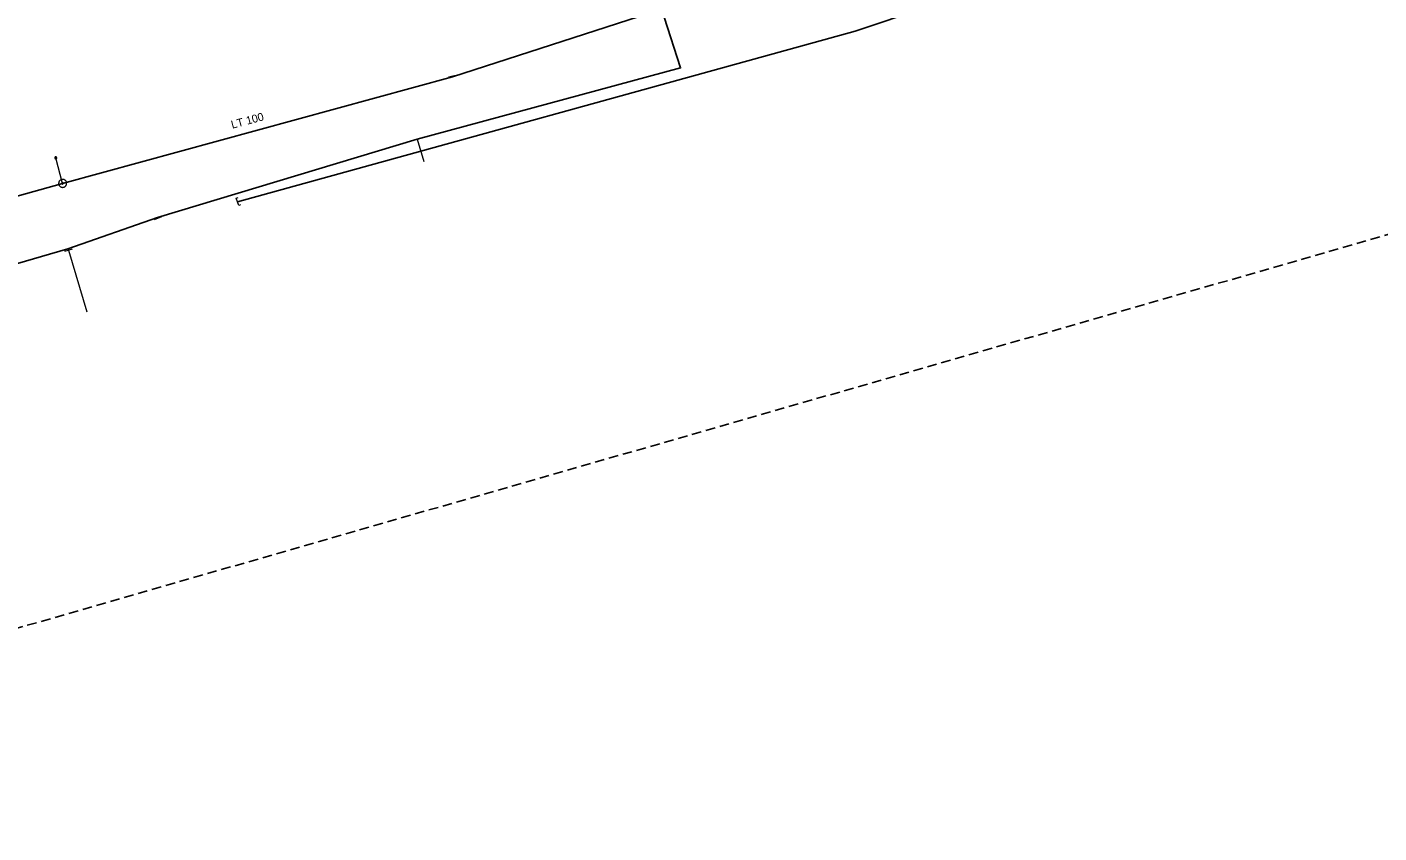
# Model space of a CAD drawing. Extents: x -690254 to -689100, y -975264 to -974703.
# Drawn here: x -690085.5 to -689916.6, y -975238.2 to -975137.4 of the extents above; entities that cross this region are included whole.
import ezdxf

# ---------------------------------------------------------------- set-up
doc = ezdxf.new("R2010")
doc.units = 0
doc.header["$LTSCALE"] = 0.4
doc.linetypes.add('MEDIUM_DASHED', pattern=[4.5, 3, -1.5])
for name, color, linetype, lineweight in [('1', 7, 'Continuous', 13), ('13', 7, 'Continuous', 13), ('14', 7, 'Continuous', 13), ('17', 7, 'Continuous', 25), ('34', 7, 'Continuous', 13), ('47', 7, 'Continuous', 13), ('63', 7, 'MEDIUM_DASHED', 25), ('9', 7, 'Continuous', 13)]:
    doc.layers.add(name, color=color, linetype=linetype, lineweight=lineweight)

msp = doc.modelspace()

# ---------------------------------------------------------------- linework, layer by layer
at = {"layer": '13'}
for p, q in [((-690036.781, -975151.448), (-690035.964, -975154.234)), ((-690080.365, -975165.332), (-690078.047, -975173.009))]:
    msp.add_line(p, q, dxfattribs=at)
at = {"layer": '14'}
for p, q in [((-690032.389, -975143.625), (-690032.41, -975143.539)), ((-690081.085, -975156.962), (-690081.941, -975153.772)), ((-690069.227, -975161.229), (-690069.19, -975161.329)), ((-690080.424, -975165.129), (-690080.365, -975165.332))]:
    msp.add_line(p, q, dxfattribs=at)
at = {"layer": '17'}
msp.add_line((-690081.085, -975156.962), (-690116.8, -975166.92), dxfattribs=at)
for points in [[(-689651.896, -975035.605), (-689702.719, -975051.484), (-689800.052, -975078.399), (-689860.597, -975095.177), (-689913.514, -975110.178), (-689937.55, -975117.079), (-689948.793, -975119.833), (-689957.109, -975122.39), (-689986.109, -975129.956), (-690002.122, -975134.99), (-690005.949, -975136.193), (-690003.879, -975142.529), (-690036.781, -975151.448), (-690069.227, -975161.229), (-690080.424, -975165.129), (-690111.773, -975174.27), (-690115.204, -975175.288), (-690118.142, -975167.265)], [(-689654.548, -975043.14), (-689663.456, -975045.689), (-689770.531, -975076.689), (-689789.368, -975082.372), (-689795.659, -975083.946), (-689875.347, -975106.869), (-689899.317, -975114.153), (-689955.443, -975128.986), (-689982.052, -975137.931), (-690059.236, -975159.265)], [(-689949.282, -975117.252), (-689986.41, -975127.792), (-690009.077, -975136.085), (-690032.389, -975143.625), (-690081.085, -975156.962)]]:
    msp.add_lwpolyline(points, dxfattribs=at)
at = {"layer": '34'}
for p, q in [((-690032.896, -975143.653), (-690031.923, -975143.425)), ((-690068.722, -975161.152), (-690069.658, -975161.504)), ((-690079.885, -975165.191), (-690080.845, -975165.471))]:
    msp.add_line(p, q, dxfattribs=at)
at = {"layer": '47'}
for points in [[(-690080.601, -975156.835), (-690080.617, -975156.785), (-690080.638, -975156.737), (-690080.664, -975156.692), (-690080.694, -975156.649), (-690080.729, -975156.61), (-690080.768, -975156.575), (-690080.81, -975156.544), (-690080.856, -975156.518), (-690080.903, -975156.496), (-690080.953, -975156.479), (-690081.004, -975156.468), (-690081.056, -975156.463), (-690081.108, -975156.462), (-690081.16, -975156.468), (-690081.211, -975156.478), (-690081.261, -975156.494), (-690081.309, -975156.515), (-690081.355, -975156.541), (-690081.397, -975156.571), (-690081.436, -975156.606), (-690081.471, -975156.645), (-690081.503, -975156.688), (-690081.529, -975156.733), (-690081.551, -975156.78), (-690081.567, -975156.83), (-690081.578, -975156.881), (-690081.584, -975156.933), (-690081.584, -975156.985), (-690081.578, -975157.037), (-690081.568, -975157.088), (-690081.552, -975157.138), (-690081.531, -975157.186), (-690081.506, -975157.232), (-690081.475, -975157.274), (-690081.44, -975157.313), (-690081.402, -975157.349), (-690081.359, -975157.38), (-690081.314, -975157.406), (-690081.266, -975157.428), (-690081.216, -975157.444), (-690081.165, -975157.455), (-690081.114, -975157.461), (-690081.061, -975157.461), (-690081.009, -975157.455), (-690080.958, -975157.445), (-690080.908, -975157.429), (-690080.86, -975157.408), (-690080.815, -975157.383), (-690080.772, -975157.352), (-690080.733, -975157.317), (-690080.697, -975157.279), (-690080.667, -975157.237), (-690080.641, -975157.191), (-690080.619, -975157.143), (-690080.602, -975157.093), (-690080.591, -975157.042), (-690080.586, -975156.991), (-690080.585, -975156.938), (-690080.591, -975156.886)], [(-690081.005, -975156.941), (-690081.007, -975156.932), (-690081.011, -975156.925), (-690081.015, -975156.918), (-690081.02, -975156.911), (-690081.026, -975156.904), (-690081.033, -975156.898), (-690081.039, -975156.893), (-690081.047, -975156.889), (-690081.055, -975156.885), (-690081.063, -975156.882), (-690081.072, -975156.881), (-690081.08, -975156.88), (-690081.088, -975156.88), (-690081.097, -975156.88), (-690081.105, -975156.882), (-690081.114, -975156.884), (-690081.121, -975156.888), (-690081.128, -975156.892), (-690081.135, -975156.897), (-690081.142, -975156.903), (-690081.148, -975156.91), (-690081.153, -975156.916), (-690081.157, -975156.924), (-690081.161, -975156.932), (-690081.164, -975156.94), (-690081.165, -975156.949), (-690081.166, -975156.957), (-690081.166, -975156.965), (-690081.166, -975156.974), (-690081.164, -975156.982), (-690081.162, -975156.991), (-690081.158, -975156.998), (-690081.154, -975157.005), (-690081.149, -975157.012), (-690081.143, -975157.019), (-690081.137, -975157.025), (-690081.13, -975157.03), (-690081.122, -975157.034), (-690081.114, -975157.038), (-690081.106, -975157.041), (-690081.097, -975157.042), (-690081.089, -975157.043), (-690081.081, -975157.043), (-690081.072, -975157.043), (-690081.064, -975157.041), (-690081.055, -975157.039), (-690081.048, -975157.035), (-690081.041, -975157.031), (-690081.034, -975157.026), (-690081.027, -975157.02), (-690081.021, -975157.014), (-690081.016, -975157.007), (-690081.012, -975156.999), (-690081.008, -975156.991), (-690081.005, -975156.983), (-690081.004, -975156.974), (-690081.003, -975156.966), (-690081.003, -975156.958), (-690081.003, -975156.949)]]:
    msp.add_lwpolyline(points, close=True, dxfattribs=at)
msp.add_lwpolyline([(-690058.844, -975159.66), (-690059.084, -975159.737), (-690059.387, -975158.792), (-690059.147, -975158.715)], dxfattribs=at)
at = {"layer": '63'}
msp.add_lwpolyline([(-690175.832, -975238.167), (-690201.511, -975156.663), (-690201.511, -975156.663), (-689696.859, -975008.171), (-689696.859, -975008.171), (-689730.354, -974917.735), (-689730.354, -974917.735), (-689127.452, -974763.66), (-689127.452, -974763.66), (-689118.52, -974838.465), (-689118.52, -974838.465), (-689624.288, -974970.21), (-689624.288, -974970.21), (-689593.026, -975070.694), (-689593.026, -975070.694)], close=True, dxfattribs=at)
at = {"layer": '9'}
for points in [[(-690082.067, -975153.772), (-690082.067, -975153.785), (-690082.065, -975153.798), (-690082.062, -975153.811), (-690082.057, -975153.823), (-690082.051, -975153.835), (-690082.044, -975153.846), (-690082.036, -975153.856), (-690082.026, -975153.866), (-690082.016, -975153.874), (-690082.005, -975153.881), (-690081.993, -975153.887), (-690081.981, -975153.892), (-690081.968, -975153.895), (-690081.955, -975153.897), (-690081.942, -975153.899), (-690081.929, -975153.898), (-690081.916, -975153.896), (-690081.903, -975153.893), (-690081.891, -975153.888), (-690081.879, -975153.882), (-690081.868, -975153.875), (-690081.858, -975153.867), (-690081.848, -975153.857), (-690081.84, -975153.847), (-690081.833, -975153.836), (-690081.827, -975153.824), (-690081.822, -975153.812), (-690081.819, -975153.799), (-690081.817, -975153.786), (-690081.815, -975153.773), (-690081.816, -975153.76), (-690081.818, -975153.747), (-690081.821, -975153.734), (-690081.826, -975153.722), (-690081.831, -975153.71), (-690081.839, -975153.699), (-690081.847, -975153.689), (-690081.857, -975153.679), (-690081.867, -975153.671), (-690081.878, -975153.664), (-690081.89, -975153.658), (-690081.902, -975153.653), (-690081.915, -975153.65), (-690081.928, -975153.648), (-690081.941, -975153.647), (-690081.954, -975153.647), (-690081.967, -975153.649), (-690081.98, -975153.652), (-690081.992, -975153.657), (-690082.004, -975153.663), (-690082.015, -975153.67), (-690082.025, -975153.678), (-690082.035, -975153.688), (-690082.043, -975153.698), (-690082.05, -975153.709), (-690082.056, -975153.721), (-690082.061, -975153.733), (-690082.064, -975153.746), (-690082.066, -975153.759)], [(-690082.047, -975153.772), (-690082.048, -975153.783), (-690082.046, -975153.794), (-690082.043, -975153.805), (-690082.039, -975153.815), (-690082.034, -975153.825), (-690082.028, -975153.834), (-690082.021, -975153.843), (-690082.013, -975153.851), (-690082.004, -975153.858), (-690081.995, -975153.864), (-690081.985, -975153.869), (-690081.975, -975153.873), (-690081.964, -975153.876), (-690081.953, -975153.879), (-690081.942, -975153.879), (-690081.931, -975153.879), (-690081.92, -975153.877), (-690081.909, -975153.874), (-690081.899, -975153.87), (-690081.889, -975153.865), (-690081.88, -975153.859), (-690081.871, -975153.852), (-690081.863, -975153.844), (-690081.856, -975153.835), (-690081.85, -975153.826), (-690081.845, -975153.816), (-690081.841, -975153.806), (-690081.838, -975153.795), (-690081.836, -975153.784), (-690081.835, -975153.773), (-690081.835, -975153.762), (-690081.837, -975153.751), (-690081.84, -975153.74), (-690081.844, -975153.73), (-690081.849, -975153.72), (-690081.855, -975153.711), (-690081.862, -975153.702), (-690081.87, -975153.694), (-690081.879, -975153.687), (-690081.888, -975153.681), (-690081.898, -975153.676), (-690081.907, -975153.672), (-690081.919, -975153.669), (-690081.929, -975153.667), (-690081.941, -975153.667), (-690081.952, -975153.666), (-690081.963, -975153.668), (-690081.974, -975153.671), (-690081.983, -975153.675), (-690081.994, -975153.68), (-690082.003, -975153.686), (-690082.012, -975153.693), (-690082.02, -975153.701), (-690082.027, -975153.71), (-690082.032, -975153.719), (-690082.038, -975153.729), (-690082.042, -975153.739), (-690082.045, -975153.75), (-690082.047, -975153.761)], [(-690082.028, -975153.772), (-690082.028, -975153.781), (-690082.027, -975153.79), (-690082.024, -975153.799), (-690082.021, -975153.807), (-690082.017, -975153.815), (-690082.012, -975153.823), (-690082.005, -975153.83), (-690082, -975153.836), (-690081.993, -975153.842), (-690081.985, -975153.847), (-690081.977, -975153.851), (-690081.969, -975153.854), (-690081.96, -975153.857), (-690081.951, -975153.858), (-690081.942, -975153.86), (-690081.933, -975153.859), (-690081.924, -975153.858), (-690081.915, -975153.855), (-690081.907, -975153.852), (-690081.899, -975153.848), (-690081.891, -975153.843), (-690081.884, -975153.837), (-690081.878, -975153.831), (-690081.872, -975153.824), (-690081.867, -975153.816), (-690081.863, -975153.808), (-690081.86, -975153.8), (-690081.857, -975153.791), (-690081.856, -975153.782), (-690081.853, -975153.773), (-690081.855, -975153.764), (-690081.856, -975153.755), (-690081.858, -975153.746), (-690081.862, -975153.738), (-690081.866, -975153.73), (-690081.871, -975153.722), (-690081.877, -975153.715), (-690081.883, -975153.709), (-690081.89, -975153.703), (-690081.898, -975153.698), (-690081.906, -975153.694), (-690081.914, -975153.691), (-690081.923, -975153.688), (-690081.932, -975153.687), (-690081.941, -975153.686), (-690081.95, -975153.686), (-690081.959, -975153.687), (-690081.968, -975153.69), (-690081.976, -975153.693), (-690081.983, -975153.697), (-690081.992, -975153.702), (-690081.999, -975153.708), (-690082.005, -975153.714), (-690082.011, -975153.721), (-690082.016, -975153.729), (-690082.02, -975153.737), (-690082.023, -975153.745), (-690082.026, -975153.754), (-690082.027, -975153.763)], [(-690082.008, -975153.772), (-690082.008, -975153.779), (-690082.007, -975153.786), (-690082.005, -975153.793), (-690082.003, -975153.799), (-690082, -975153.805), (-690081.996, -975153.811), (-690081.992, -975153.817), (-690081.987, -975153.822), (-690081.981, -975153.826), (-690081.975, -975153.83), (-690081.969, -975153.833), (-690081.963, -975153.836), (-690081.956, -975153.837), (-690081.949, -975153.84), (-690081.942, -975153.84), (-690081.934, -975153.84), (-690081.928, -975153.838), (-690081.921, -975153.837), (-690081.915, -975153.834), (-690081.907, -975153.831), (-690081.903, -975153.827), (-690081.897, -975153.823), (-690081.892, -975153.818), (-690081.888, -975153.812), (-690081.884, -975153.806), (-690081.88, -975153.8), (-690081.878, -975153.794), (-690081.876, -975153.787), (-690081.875, -975153.78), (-690081.874, -975153.773), (-690081.874, -975153.766), (-690081.875, -975153.759), (-690081.877, -975153.752), (-690081.88, -975153.746), (-690081.883, -975153.739), (-690081.887, -975153.734), (-690081.891, -975153.728), (-690081.896, -975153.723), (-690081.902, -975153.719), (-690081.907, -975153.715), (-690081.914, -975153.712), (-690081.92, -975153.709), (-690081.927, -975153.707), (-690081.934, -975153.706), (-690081.941, -975153.706), (-690081.948, -975153.706), (-690081.955, -975153.706), (-690081.962, -975153.708), (-690081.968, -975153.711), (-690081.974, -975153.714), (-690081.98, -975153.718), (-690081.986, -975153.722), (-690081.991, -975153.727), (-690081.995, -975153.733), (-690081.999, -975153.738), (-690082.002, -975153.745), (-690082.005, -975153.751), (-690082.005, -975153.758), (-690082.008, -975153.765)], [(-690081.988, -975153.772), (-690081.988, -975153.777), (-690081.988, -975153.782), (-690081.987, -975153.787), (-690081.985, -975153.791), (-690081.983, -975153.796), (-690081.98, -975153.8), (-690081.977, -975153.803), (-690081.973, -975153.807), (-690081.97, -975153.81), (-690081.966, -975153.813), (-690081.961, -975153.815), (-690081.956, -975153.817), (-690081.952, -975153.818), (-690081.947, -975153.82), (-690081.942, -975153.82), (-690081.937, -975153.82), (-690081.932, -975153.819), (-690081.927, -975153.818), (-690081.923, -975153.816), (-690081.918, -975153.814), (-690081.914, -975153.811), (-690081.91, -975153.808), (-690081.907, -975153.804), (-690081.904, -975153.801), (-690081.901, -975153.797), (-690081.899, -975153.792), (-690081.897, -975153.788), (-690081.896, -975153.783), (-690081.895, -975153.778), (-690081.894, -975153.773), (-690081.894, -975153.768), (-690081.895, -975153.763), (-690081.896, -975153.758), (-690081.898, -975153.754), (-690081.9, -975153.749), (-690081.903, -975153.745), (-690081.906, -975153.741), (-690081.909, -975153.738), (-690081.913, -975153.735), (-690081.917, -975153.732), (-690081.922, -975153.73), (-690081.926, -975153.728), (-690081.931, -975153.727), (-690081.936, -975153.726), (-690081.941, -975153.726), (-690081.946, -975153.726), (-690081.951, -975153.727), (-690081.956, -975153.727), (-690081.96, -975153.729), (-690081.965, -975153.731), (-690081.969, -975153.734), (-690081.972, -975153.737), (-690081.976, -975153.74), (-690081.978, -975153.744), (-690081.982, -975153.748), (-690081.983, -975153.753), (-690081.986, -975153.757), (-690081.987, -975153.762), (-690081.988, -975153.767)], [(-690081.968, -975153.772), (-690081.968, -975153.775), (-690081.969, -975153.778), (-690081.968, -975153.78), (-690081.967, -975153.783), (-690081.966, -975153.786), (-690081.964, -975153.788), (-690081.962, -975153.79), (-690081.96, -975153.792), (-690081.958, -975153.794), (-690081.956, -975153.796), (-690081.953, -975153.798), (-690081.95, -975153.799), (-690081.948, -975153.799), (-690081.945, -975153.8), (-690081.942, -975153.8), (-690081.939, -975153.8), (-690081.936, -975153.8), (-690081.933, -975153.799), (-690081.931, -975153.798), (-690081.928, -975153.797), (-690081.926, -975153.795), (-690081.923, -975153.793), (-690081.921, -975153.791), (-690081.92, -975153.789), (-690081.918, -975153.787), (-690081.917, -975153.784), (-690081.915, -975153.781), (-690081.915, -975153.779), (-690081.914, -975153.776), (-690081.913, -975153.773), (-690081.914, -975153.77), (-690081.914, -975153.767), (-690081.915, -975153.764), (-690081.916, -975153.762), (-690081.917, -975153.759), (-690081.919, -975153.757), (-690081.92, -975153.754), (-690081.922, -975153.752), (-690081.925, -975153.751), (-690081.927, -975153.749), (-690081.929, -975153.748), (-690081.932, -975153.747), (-690081.934, -975153.746), (-690081.938, -975153.746), (-690081.941, -975153.745), (-690081.944, -975153.746), (-690081.947, -975153.745), (-690081.949, -975153.747), (-690081.952, -975153.747), (-690081.955, -975153.748), (-690081.956, -975153.75), (-690081.959, -975153.751), (-690081.961, -975153.753), (-690081.963, -975153.756), (-690081.965, -975153.758), (-690081.966, -975153.761), (-690081.967, -975153.763), (-690081.968, -975153.766), (-690081.968, -975153.769)], [(-690081.949, -975153.772), (-690081.949, -975153.774), (-690081.949, -975153.774), (-690081.948, -975153.774), (-690081.948, -975153.776), (-690081.949, -975153.777), (-690081.947, -975153.777), (-690081.947, -975153.777), (-690081.947, -975153.779), (-690081.947, -975153.779), (-690081.946, -975153.78), (-690081.944, -975153.78), (-690081.944, -975153.78), (-690081.944, -975153.781), (-690081.942, -975153.781), (-690081.942, -975153.781), (-690081.941, -975153.781), (-690081.94, -975153.781), (-690081.94, -975153.78), (-690081.939, -975153.78), (-690081.937, -975153.78), (-690081.937, -975153.779), (-690081.937, -975153.779), (-690081.936, -975153.778), (-690081.936, -975153.778), (-690081.934, -975153.777), (-690081.934, -975153.776), (-690081.933, -975153.775), (-690081.933, -975153.775), (-690081.933, -975153.774), (-690081.933, -975153.773), (-690081.933, -975153.772), (-690081.933, -975153.771), (-690081.933, -975153.771), (-690081.934, -975153.77), (-690081.934, -975153.769), (-690081.934, -975153.768), (-690081.934, -975153.768), (-690081.936, -975153.767), (-690081.936, -975153.767), (-690081.937, -975153.766), (-690081.938, -975153.766), (-690081.939, -975153.765), (-690081.939, -975153.765), (-690081.94, -975153.765), (-690081.941, -975153.765), (-690081.942, -975153.765), (-690081.943, -975153.765), (-690081.943, -975153.765), (-690081.944, -975153.766), (-690081.945, -975153.765), (-690081.946, -975153.767), (-690081.946, -975153.767), (-690081.947, -975153.767), (-690081.947, -975153.767), (-690081.948, -975153.769), (-690081.948, -975153.77), (-690081.948, -975153.771), (-690081.949, -975153.771), (-690081.949, -975153.772)]]:
    msp.add_lwpolyline(points, close=True, dxfattribs=at)

# ---------------------------------------------------------------- texts
at = {"layer": '1'}
msp.add_text('LT 100', height=1, rotation=15, dxfattribs=at).set_placement((-690059.891, -975150.135))

doc.saveas('drawing.dxf')
